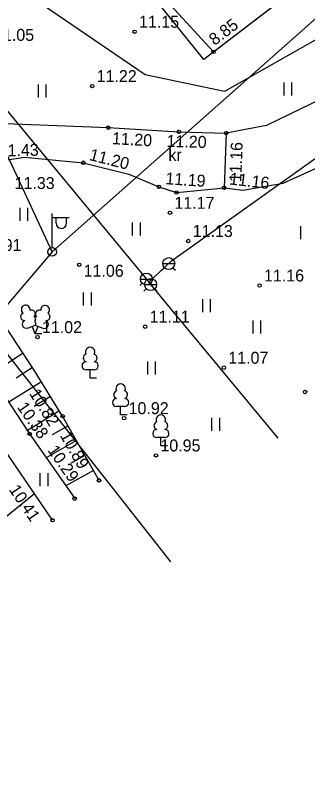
# Model space of a CAD drawing. Extents: x 554198 to 554371, y 6593448 to 6593563.
# Drawn here: x 554312.55 to 554329.64, y 6593489.56 to 6593534.71 of the extents above; entities that cross this region are included whole.
import ezdxf

# ---------------------------------------------------------------- set-up
doc = ezdxf.new("R2010")
doc.units = 0
for name, color, linetype in [('AED', 7, 'Continuous'), ('HALJASTUS', 7, 'Continuous'), ('KORGUS-EH2000', 7, 'Continuous'), ('MPOHULIIN', 7, 'Continuous'), ('PIIR', 7, 'Continuous'), ('POST', 7, 'Continuous'), ('PUU', 7, 'Continuous'), ('RELJEEF', 7, 'Continuous'), ('SIOHULIIN', 7, 'Continuous'), ('TEE', 7, 'Continuous'), ('VKAEV', 7, 'Continuous'), ('VTRASS', 7, 'Continuous')]:
    doc.layers.add(name, color=color, linetype=linetype)

msp = doc.modelspace()

# ---------------------------------------------------------------- linework, layer by layer
at = {"layer": 'AED'}
msp.add_lwpolyline([(554313.529, 6593544.411), (554315.53, 6593541.932), (554324.135, 6593532.582), (554324.882, 6593533.149), (554330.278, 6593537.293)], dxfattribs=at)
at = {"layer": 'HALJASTUS'}
for p, q in [((554328.25, 6593530.781), (554328.25, 6593530.02)), ((554328.705, 6593530.781), (554328.705, 6593530.02)), ((554313.875, 6593530.675), (554313.875, 6593529.914)), ((554314.33, 6593530.675), (554314.33, 6593529.914)), ((554312.8, 6593523.458), (554312.8, 6593522.697)), ((554313.255, 6593523.458), (554313.255, 6593522.697)), ((554319.385, 6593522.609), (554319.385, 6593521.847)), ((554319.84, 6593522.609), (554319.84, 6593521.847)), ((554329.228, 6593522.396), (554329.228, 6593521.635)), ((554316.517, 6593518.501), (554316.517, 6593517.74)), ((554316.972, 6593518.501), (554316.972, 6593517.74)), ((554323.492, 6593518.112), (554323.492, 6593517.351)), ((554323.948, 6593518.112), (554323.948, 6593517.351)), ((554326.431, 6593516.873), (554326.431, 6593516.112)), ((554326.886, 6593516.873), (554326.886, 6593516.112)), ((554320.27, 6593514.465), (554320.27, 6593513.704)), ((554320.726, 6593514.465), (554320.726, 6593513.704)), ((554324.024, 6593511.172), (554324.024, 6593510.411)), ((554324.479, 6593511.172), (554324.479, 6593510.411)), ((554313.982, 6593507.938), (554313.982, 6593507.177)), ((554314.437, 6593507.938), (554314.437, 6593507.177))]:
    msp.add_line(p, q, dxfattribs=at)
msp.add_lwpolyline([(554332.43, 6593534.6), (554324.779, 6593530.257), (554320.14, 6593531.245), (554313.27, 6593535.93)], dxfattribs=at)
at = {"layer": 'KORGUS-EH2000'}
for centre in [(554319.52, 6593533.76), (554324.135, 6593532.582), (554317.04, 6593530.58), (554317.98, 6593528.15), (554322.11, 6593527.91), (554324.87, 6593527.83), (554316.52, 6593526.1), (554320.94, 6593524.69), (554321.97, 6593524.35), (554324.75, 6593524.63), (554321.59, 6593523.17), (554322.66, 6593521.52), (554316.28, 6593520.13), (554326.83, 6593518.92), (554320.14, 6593516.51), (554313.84, 6593515.9), (554324.74, 6593514.11), (554329.49, 6593512.69), (554315.31, 6593511.28), (554318.91, 6593511.16), (554313.38, 6593510.25), (554320.77, 6593508.98), (554317.438, 6593507.521), (554316.014, 6593506.453), (554314.721, 6593505.189)]:
    msp.add_circle(centre, 0.1, dxfattribs=at)
at = {"layer": 'MPOHULIIN'}
msp.add_lwpolyline([(554314.701, 6593520.885), (554342.904, 6593545.872)], dxfattribs=at)
at = {"layer": 'PIIR'}
for p, q in [((554323.57, 6593532.14), (554309.663, 6593549.406)), ((554343.27, 6593547.24), (554323.57, 6593532.14)), ((554309.59, 6593518.04), (554321.626, 6593502.754))]:
    msp.add_line(p, q, dxfattribs=at)
at = {"layer": 'POST'}
for p, q in [((554314.701, 6593521.135), (554314.701, 6593523.135)), ((554314.701, 6593522.885), (554315.701, 6593522.885)), ((554314.928, 6593522.564), (554314.928, 6593522.885)), ((554315.54, 6593522.564), (554315.54, 6593522.885))]:
    msp.add_line(p, q, dxfattribs=at)
msp.add_circle((554314.701, 6593520.885), 0.25, dxfattribs=at)
msp.add_arc((554315.234, 6593522.564), 0.306, 180, 0, dxfattribs=at)
at = {"layer": 'PUU'}
for p, q in [((554313.265, 6593516.431), (554313.71, 6593516.606)), ((554313.705, 6593516.096), (554313.53, 6593516.536)), ((554313.705, 6593516.096), (554313.885, 6593516.536)), ((554313.71, 6593516.606), (554314.15, 6593516.426)), ((554314.085, 6593516.096), (554313.705, 6593516.096)), ((554317.158, 6593513.983), (554316.678, 6593513.983)), ((554316.918, 6593513.508), (554316.918, 6593513.983)), ((554317.298, 6593513.508), (554316.918, 6593513.508)), ((554318.943, 6593511.838), (554318.463, 6593511.838)), ((554318.703, 6593511.363), (554318.703, 6593511.838)), ((554319.083, 6593511.363), (554318.703, 6593511.363)), ((554321.296, 6593510.025), (554320.816, 6593510.025)), ((554321.056, 6593509.55), (554321.056, 6593510.025)), ((554321.436, 6593509.55), (554321.056, 6593509.55))]:
    msp.add_line(p, q, dxfattribs=at)
msp.add_lwpolyline([(554313.71, 6593517.101), (554313.69, 6593517.026), (554313.69, 6593517.006), (554313.7, 6593516.976), (554313.72, 6593516.941), (554313.725, 6593516.921), (554313.71, 6593516.886), (554313.685, 6593516.836), (554313.68, 6593516.811), (554313.685, 6593516.796), (554313.695, 6593516.766), (554313.73, 6593516.706), (554313.735, 6593516.686), (554313.73, 6593516.666), (554313.715, 6593516.631), (554313.71, 6593516.606)], dxfattribs=at)
for centre, radius, start, end in [((554313.148, 6593517.51), 0.256, 111.5027, 232.5173), ((554313.148, 6593517.51), 0.256, 350.4856, 111.5002), ((554314.284, 6593517.501), 0.256, 67.6168, 188.6314), ((554314.284, 6593517.501), 0.256, 306.5997, 67.6143), ((554313.074, 6593517.099), 0.224, 111.4304, 274.4987), ((554313.483, 6593517.26), 0.224, 308.5041, 111.5725), ((554313.946, 6593517.255), 0.225, 67.7016, 230.5126), ((554314.351, 6593517.089), 0.224, 264.6183, 67.6866), ((554313.179, 6593516.654), 0.237, 111.5014, 291.5004), ((554313.709, 6593516.863), 0.237, 66.7655, 111.5015), ((554314.24, 6593516.646), 0.237, 247.6166, 67.6155), ((554316.918, 6593515.028), 0.277, 332.5799, 207.4201), ((554316.748, 6593514.681), 0.233, 109.0217, 253.1415), ((554317.088, 6593514.681), 0.233, 286.8508, 70.9859), ((554316.681, 6593514.22), 0.238, 90.0016, 269.3953), ((554317.155, 6593514.22), 0.238, 270.6047, 89.9984), ((554318.703, 6593512.883), 0.277, 332.5799, 207.4201), ((554318.533, 6593512.536), 0.233, 109.0217, 253.1415), ((554318.873, 6593512.536), 0.233, 286.8508, 70.9859), ((554318.466, 6593512.075), 0.238, 90.0016, 269.3953), ((554318.94, 6593512.075), 0.238, 270.6047, 89.9984), ((554321.056, 6593511.07), 0.277, 332.5799, 207.4201), ((554320.886, 6593510.723), 0.233, 109.0217, 253.1415), ((554321.226, 6593510.723), 0.233, 286.8508, 70.9859), ((554320.819, 6593510.262), 0.238, 90.0016, 269.3953), ((554321.293, 6593510.262), 0.238, 270.6047, 89.9984)]:
    msp.add_arc(centre, radius, start, end, dxfattribs=at)
at = {"layer": 'RELJEEF'}
for p, q in [((554312.996, 6593514.967), (554311.087, 6593513.709)), ((554313.546, 6593514.131), (554312.593, 6593513.504)), ((554314.076, 6593513.283), (554312.154, 6593512.099)), ((554314.6, 6593512.432), (554313.654, 6593511.849)), ((554315.125, 6593511.58), (554313.26, 6593510.431)), ((554315.629, 6593510.717), (554314.705, 6593510.194)), ((554316.121, 6593509.847), (554314.354, 6593508.846)), ((554316.614, 6593508.976), (554315.77, 6593508.499)), ((554317.107, 6593508.106), (554315.499, 6593507.196)), ((554310.199, 6593503.956), (554313.655, 6593506.758))]:
    msp.add_line(p, q, dxfattribs=at)
for points in [[(554317.438, 6593507.521), (554315.31, 6593511.28), (554313.652, 6593513.971), (554310.57, 6593518.65), (554307.568, 6593523.452), (554307.04, 6593524.213)], [(554304.907, 6593522.548), (554305.968, 6593521.122), (554308.55, 6593517.48), (554311.096, 6593513.696), (554313.38, 6593510.25), (554316.014, 6593506.453)], [(554314.721, 6593505.189), (554311.86, 6593509.4), (554309.432, 6593513.141), (554306.36, 6593515.97), (554302.586, 6593519.337), (554301.632, 6593520.188)]]:
    msp.add_lwpolyline(points, dxfattribs=at)
at = {"layer": 'SIOHULIIN'}
for points in [[(554314.701, 6593520.885), (554304.707, 6593542.403)], [(554314.701, 6593520.885), (554283.22, 6593483.889)]]:
    msp.add_lwpolyline(points, dxfattribs=at)
at = {"layer": 'TEE'}
for points in [[(554330.49, 6593529.85), (554327.24, 6593528.27), (554324.87, 6593527.83), (554324.75, 6593524.63), (554325.85, 6593524.5), (554328.21, 6593524.9), (554331.35, 6593526.32)], [(554309.16, 6593528.115), (554311.97, 6593528.39), (554317.98, 6593528.15), (554322.11, 6593527.91), (554324.87, 6593527.83)], [(554311.427, 6593526.164), (554313.1, 6593526.42), (554316.52, 6593526.1), (554319.19, 6593525.42), (554320.94, 6593524.69), (554321.97, 6593524.35), (554324.187, 6593524.57), (554324.75, 6593524.63)]]:
    msp.add_lwpolyline(points, dxfattribs=at)
at = {"layer": 'VKAEV'}
for p, q in [((554321.27, 6593519.953), (554321.13, 6593519.813)), ((554321.168, 6593520.2), (554321.868, 6593520.2)), ((554321.765, 6593519.953), (554321.905, 6593519.813)), ((554319.96, 6593519.05), (554319.82, 6593518.91)), ((554319.858, 6593519.297), (554320.558, 6593519.297)), ((554320.455, 6593519.05), (554320.595, 6593518.91)), ((554320.204, 6593518.726), (554320.064, 6593518.586)), ((554320.101, 6593518.973), (554320.801, 6593518.973)), ((554320.699, 6593518.726), (554320.839, 6593518.586))]:
    msp.add_line(p, q, dxfattribs=at)
for centre in [(554321.518, 6593520.2), (554320.208, 6593519.297), (554320.451, 6593518.973)]:
    msp.add_circle(centre, 0.35, dxfattribs=at)
at = {"layer": 'VTRASS'}
for points in [[(554320.351, 6593519.114), (554321.687, 6593520.357), (554343.297, 6593535.785), (554362.436, 6593550.651)], [(554301.662, 6593541.71), (554320.208, 6593519.297), (554320.351, 6593519.114), (554320.451, 6593518.973), (554327.895, 6593509.98)]]:
    msp.add_lwpolyline(points, dxfattribs=at)

# ---------------------------------------------------------------- texts
at = {"layer": 'KORGUS-EH2000'}
for s, p in [(' 11.15 ', (554319.52, 6593533.993)), (' 11.05 ', (554311.04, 6593533.223)), (' 11.22 ', (554317.04, 6593530.813)), (' 11.33 ', (554312.24, 6593524.56)), (' 11.17 ', (554321.59, 6593523.403)), (' 11.13 ', (554322.66, 6593521.753)), (' 10.91 ', (554310.3, 6593520.933)), (' 11.06 ', (554316.28, 6593519.43)), (' 11.16 ', (554326.83, 6593519.153)), (' 11.11 ', (554320.14, 6593516.743)), (' 11.02 ', (554313.84, 6593516.133)), (' 11.07 ', (554324.74, 6593514.343)), (' 10.92 ', (554318.91, 6593511.393)), (' 10.95 ', (554320.77, 6593509.213))]:
    msp.add_text(s, height=0.7, dxfattribs=at).set_placement(p)
for s, rotation, p in [(' 8.85 ', 37.1998, (554323.994, 6593532.768)), (' 11.20 ', 356.6742, (554317.925, 6593527.202)), (' 11.20 ', 358.3397, (554321.122, 6593527.032)), (' 11.43 ', 1.3163, (554311.317, 6593526.45)), (' 11.16 ', 87.8524, (554325.749, 6593524.694)), (' 11.20 ', 345.7116, (554316.578, 6593526.326)), (' 11.19 ', 356.0814, (554321.049, 6593524.86)), (' 11.16 ', 353.2599, (554324.777, 6593524.862)), (' 10.82 ', 301.6384, (554313.194, 6593512.828)), (' 10.38 ', 304.7493, (554312.471, 6593512.02)), (' 10.89 ', 299.5145, (554315.005, 6593510.377)), (' 10.29 ', 304.7493, (554314.253, 6593509.496)), (' 10.41 ', 304.1926, (554311.994, 6593507.195))]:
    msp.add_text(s, height=0.7, rotation=rotation, dxfattribs=at).set_placement(p)
at = {"layer": 'TEE'}
msp.add_text('kr', height=0.7, dxfattribs=at).set_placement((554321.497, 6593526.207))

doc.saveas('drawing.dxf')
